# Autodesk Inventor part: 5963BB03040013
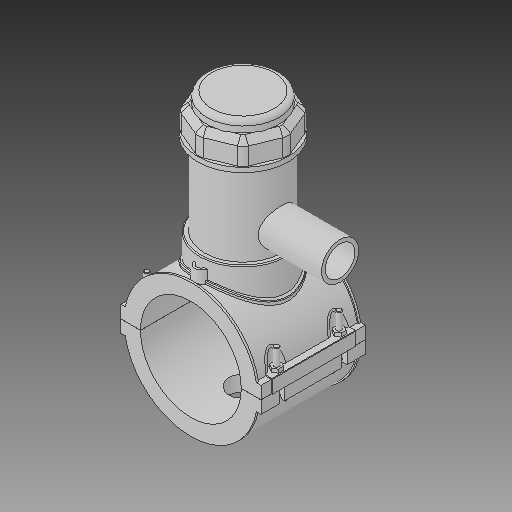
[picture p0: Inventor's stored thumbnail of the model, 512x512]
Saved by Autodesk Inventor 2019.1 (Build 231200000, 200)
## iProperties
Created: 2017-07
Part Number: 5963BB03040013
Material: Generic
Description: PLASSON TAPPING SADDLE 4''IPS x 1 1/4''IPS
Document SubType Name: Modeling
Designer: KIM
Mass: 1712.7 g
Surface Area: 2671.49 cm^2
Volume: 1712.7 cm^3
Density: 1 g/cm^3
Appearance: Default
Author: KIM
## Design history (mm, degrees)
derived "5963B.ipt"
feature "Solid1::5963B.ipt"
feature "Solid2::5963B.ipt"
feature "Solid4::5963B.ipt"
feature "Solid5::5963B.ipt"
tag "TaggingFeature1"
body "Solid1"
body "Solid2"
other parameters: "d0" = 114.1, "d2" = 159.004, "d3" = 28.525, "d4" = 118.11, "d5" = 0, "d6" = 0.1, "d8" = 0, "d19" = 6, "d20" = 6, "d21" = 70.866, "d23" = 0, "d24" = 35.433, "d26" = 0, "d29" = 3, "d30" = 38.03333, "d31" = 6, "d32" = 0, "d33" = 0, "d34" = 0.6, "d40" = 77.1316, "d41" = 102.69, "d43" = 0, "d45" = 0, "d47" = 145.031, "d70" = 15, "d72" = 0, "d73" = 6, "d75" = 5, "d76" = 0, "d77" = 5.705, "d78" = 87.05, "d79" = 15, "d80" = 47.244, "d82" = 5 deg, "d84" = 4, "d85" = 14, "d86" = 0, "d87" = 3, "d88" = 0, "d89" = 1, "d90" = 1, "d91" = 94.488, "d92" = 0, "d93" = 0.5, "d94" = 60.05263, "d96" = 151.2966, "d97" = 2.3622, "d98" = 0, "d102" = 1.141, "d120" = 140 deg, "d121" = 24.228, "d122" = 20 deg, "d123" = 296.66, "d124" = 88.998, "d126" = 0, "d143" = 117.523, "d145" = 26.33077, "d149" = 1.7115, "d150" = 28.96385, "d153" = 118.11, "d154" = 0, "d156" = 74.165, "d157" = 160 deg, "d159" = 6.846, "d161" = 1.7115, "d162" = 70.866, "d163" = 0, "d164" = 57.05, "d167" = 11.41, "d168" = 72.3561, "d170" = 3.2805, "d172" = 0, "d173" = 1, "d175" = 57.05, "d176" = 20 deg, "d177" = 7.987, "d178" = 34.23, "d180" = 0, "d183" = 13.692, "d184" = 6.3896, "d185" = 38.38575, "d186" = 38.38575, "d187" = 74.165, "d188" = 10.269, "d189" = 7.987, "d190" = 0, "d191" = 111.2475, "d193" = 6.1236, "d194" = 4.13385, "d195" = 90 deg, "d197" = 0, "d199" = 0, "d200" = 17.115, "d202" = 0, "d203" = 177.038, "d204" = 97.5555, "d205" = 71.883, "d206" = 87.2865, "d207" = 132.7785, "d208" = 138.08964, "d209" = 164.64534, "d210" = 88.3134, "d211" = 102.69, "d212" = 82.152, "d213" = 39.5766, "d216" = 0, "d217" = 11.41, "d218" = 5.705, "d219" = 1.141, "d222" = 114.1, "d224" = 0, "d230" = 6.846, "d233" = 6, "d236" = 79.502, "d237" = 35.433, "d238" = 6.02433, "d240" = 35.433, "d241" = 35.433, "d242" = 35.433, "d243" = 6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
